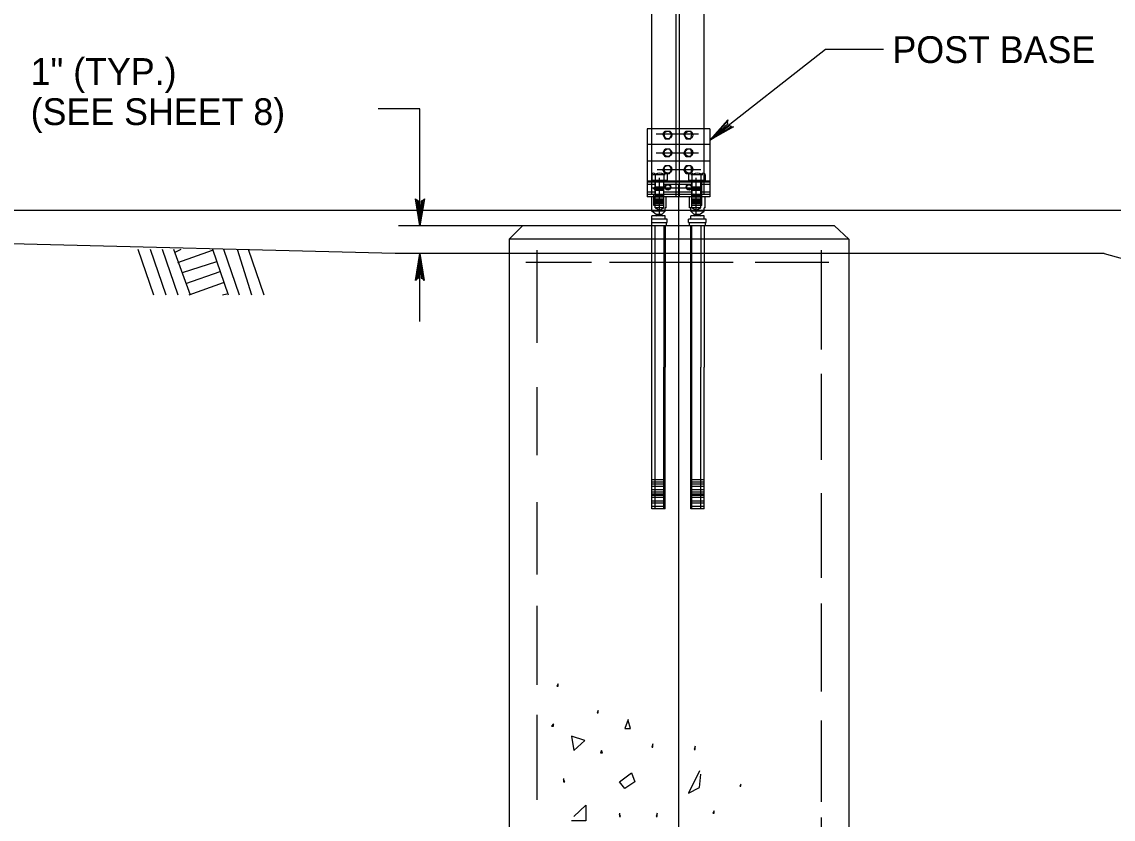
# Model space of a CAD drawing. Extents: x 637580 to 641008, y 294594 to 295782.
# Drawn here: x 637867.6 to 637989.9, y 295392.1 to 295481.5 of the extents above; entities that cross this region are included whole.
import ezdxf

# ---------------------------------------------------------------- set-up
doc = ezdxf.new("R2010")
doc.units = 0
for name, color, linetype in [('1', 7, 'Continuous'), ('2', 7, 'Continuous'), ('3', 7, 'Continuous')]:
    doc.layers.add(name, color=color, linetype=linetype)

# ---------------------------------------------------------------- blocks, each defined once
blk = doc.blocks.new('RARROW')
at = {"layer": '3'}
blk.add_lwpolyline([(-2.2695, 0.285), (-2.184875, 0.12075), (0, 0), (-2.2695, 0.285), (-2.38575, 0.384625), (0, 0), (-2.183125, -0.108), (-2.262875, -0.2705), (0, 0), (-2.38575, -0.379125), (-2.262875, -0.2705)], dxfattribs=at)

msp = doc.modelspace()

# ---------------------------------------------------------------- linework, layer by layer
at = {"layer": '1'}
for p, q in [((637880.56, 295456), (637882.31, 295450.88)), ((637881.94, 295456), (637883.69, 295450.88)), ((637883.31, 295456), (637885.06, 295450.88)), ((637884.56, 295456), (637886.44, 295450.88)), ((637884.69, 295455.63), (637885.44, 295456)), ((637885.06, 295454.5), (637888.94, 295455.88)), ((637888.94, 295456), (637890.69, 295450.88)), ((637890.19, 295456), (637891.94, 295450.88)), ((637891.69, 295456), (637893.31, 295450.88)), ((637892.94, 295456), (637894.69, 295450.88)), ((637885.56, 295453.38), (637889.44, 295454.63)), ((637885.94, 295452.13), (637889.81, 295453.5)), ((637886.31, 295450.88), (637890.19, 295452.25)), ((637890.06, 295450.88), (637890.56, 295451))]:
    msp.add_line(p, q, dxfattribs=at)
at = {"layer": '2'}
for p, q in [((637940.94, 295461.88), (637940.94, 295676.88)), ((637941.31, 295461.88), (637941.31, 295676.88)), ((637938.19, 295469.5), (637938.19, 295549.5)), ((637944.06, 295469.5), (637944.06, 295549.5)), ((637957.69, 295478.38), (637944.69, 295468.24)), ((637964.19, 295478.38), (637957.69, 295478.38)), ((637912.19, 295471.75), (637907.5, 295471.75)), ((637912.19, 295458.63), (637912.19, 295471.75)), ((637944.69, 295469.5), (637937.69, 295469.5)), ((637937.69, 295469.5), (637937.69, 295462.13)), ((637938.19, 295462.13), (637938.19, 295469.5)), ((637939.44, 295468.88), (637939.69, 295469.25)), ((637939.56, 295468.88), (637939.69, 295469.25)), ((637939.69, 295469.25), (637940.19, 295469.25)), ((637939.69, 295469.25), (637940.19, 295469.25)), ((637940.19, 295469.25), (637940.44, 295468.88)), ((637940.44, 295468.88), (637940.19, 295469.25)), ((637941.81, 295468.88), (637942.06, 295469.25)), ((637941.81, 295468.88), (637942.06, 295469.25)), ((637942.06, 295469.25), (637942.56, 295469.25)), ((637942.06, 295469.25), (637942.56, 295469.25)), ((637942.56, 295469.25), (637942.69, 295468.88)), ((637942.69, 295468.88), (637942.56, 295469.25)), ((637944.06, 295462.13), (637944.06, 295469.5)), ((637944.69, 295469.5), (637944.69, 295462.13)), ((637943.44, 295468.88), (637938.69, 295468.88)), ((637939.69, 295468.38), (637939.44, 295468.88)), ((637939.56, 295468.88), (637939.69, 295468.38)), ((637939.69, 295468.38), (637940.19, 295468.38)), ((637939.69, 295468.38), (637940.19, 295468.38)), ((637939.94, 295468.88), (637939.94, 295468.88)), ((637939.94, 295468.88), (637939.94, 295468.88)), ((637939.94, 295468.88), (637939.94, 295468.88)), ((637940.19, 295468.38), (637940.44, 295468.88)), ((637940.19, 295468.38), (637940.44, 295468.88)), ((637941.81, 295468.88), (637942.06, 295468.38)), ((637942.06, 295468.38), (637941.81, 295468.88)), ((637942.06, 295468.38), (637942.56, 295468.38)), ((637942.06, 295468.38), (637942.56, 295468.38)), ((637942.31, 295468.88), (637942.31, 295468.88)), ((637942.31, 295468.88), (637942.31, 295468.88)), ((637942.31, 295468.88), (637942.31, 295468.88)), ((637942.56, 295468.38), (637942.69, 295468.88)), ((637942.56, 295468.38), (637942.69, 295468.88)), ((637944.69, 295467.75), (637937.69, 295467.75)), ((637943.44, 295466.75), (637938.69, 295466.75)), ((637939.44, 295466.75), (637939.69, 295467.25)), ((637939.69, 295466.38), (637939.44, 295466.75)), ((637939.56, 295466.75), (637939.69, 295467.25)), ((637939.56, 295466.75), (637939.69, 295466.38)), ((637939.69, 295467.25), (637940.19, 295467.25)), ((637939.69, 295467.25), (637940.19, 295467.25)), ((637939.94, 295466.75), (637939.94, 295466.75)), ((637939.94, 295466.75), (637939.94, 295466.75)), ((637939.94, 295466.75), (637939.94, 295466.75)), ((637940.19, 295467.25), (637940.44, 295466.75)), ((637940.44, 295466.75), (637940.19, 295467.25)), ((637940.19, 295466.38), (637940.44, 295466.75)), ((637940.19, 295466.38), (637940.44, 295466.75)), ((637941.81, 295466.75), (637942.06, 295467.25)), ((637941.81, 295466.75), (637942.06, 295467.25)), ((637941.81, 295466.75), (637942.06, 295466.38)), ((637942.06, 295466.38), (637941.81, 295466.75)), ((637942.06, 295467.25), (637942.56, 295467.25)), ((637942.06, 295467.25), (637942.56, 295467.25)), ((637942.31, 295466.75), (637942.31, 295466.75)), ((637942.31, 295466.75), (637942.31, 295466.75)), ((637942.31, 295466.75), (637942.31, 295466.75)), ((637942.56, 295467.25), (637942.69, 295466.75)), ((637942.69, 295466.75), (637942.56, 295467.25)), ((637942.56, 295466.38), (637942.69, 295466.75)), ((637942.56, 295466.38), (637942.69, 295466.75)), ((637944.69, 295465.88), (637937.69, 295465.88)), ((637939.69, 295466.38), (637940.19, 295466.38)), ((637939.69, 295466.38), (637940.19, 295466.38)), ((637942.06, 295466.38), (637942.56, 295466.38)), ((637942.06, 295466.38), (637942.56, 295466.38)), ((637938.19, 295464.38), (637938.19, 295464.38)), ((637938.19, 295464.38), (637938.19, 295463.75)), ((637938.31, 295464.38), (637938.31, 295464.38)), ((637938.31, 295464.38), (637938.56, 295464.38)), ((637938.56, 295464.38), (637938.56, 295463.75)), ((637938.56, 295464.38), (637939.56, 295464.38)), ((637938.56, 295464.38), (637938.56, 295464.38)), ((637943.69, 295464.88), (637938.81, 295464.88)), ((637939.06, 295464.38), (637939.06, 295464.38)), ((637939.44, 295464.88), (637939.69, 295465.38)), ((637939.69, 295464.5), (637939.44, 295464.88)), ((637939.56, 295464.88), (637939.69, 295465.38)), ((637939.56, 295464.88), (637939.69, 295464.5)), ((637939.56, 295464.38), (637939.56, 295463.75)), ((637939.56, 295464.38), (637939.56, 295464.38)), ((637939.56, 295464.38), (637939.69, 295464.38)), ((637939.69, 295465.38), (637940.19, 295465.38)), ((637939.69, 295465.38), (637940.19, 295465.38)), ((637939.69, 295464.5), (637940.19, 295464.5)), ((637939.69, 295464.5), (637940.19, 295464.5)), ((637939.69, 295464.38), (637939.69, 295464.38)), ((637939.94, 295464.88), (637939.94, 295464.88)), ((637939.94, 295464.88), (637939.94, 295464.88)), ((637939.94, 295464.88), (637939.94, 295464.88)), ((637939.94, 295464.38), (637939.94, 295464.38)), ((637939.94, 295464.38), (637939.94, 295463.75)), ((637940.19, 295465.38), (637940.44, 295464.88)), ((637940.44, 295464.88), (637940.19, 295465.38)), ((637940.19, 295464.5), (637940.44, 295464.88)), ((637940.19, 295464.5), (637940.44, 295464.88)), ((637941.81, 295464.88), (637942.06, 295465.38)), ((637941.81, 295464.88), (637942.06, 295465.38)), ((637941.81, 295464.88), (637942.06, 295464.5)), ((637942.06, 295464.5), (637941.81, 295464.88)), ((637942.06, 295465.38), (637942.56, 295465.38)), ((637942.06, 295465.38), (637942.56, 295465.38)), ((637942.06, 295464.5), (637942.56, 295464.5)), ((637942.06, 295464.5), (637942.56, 295464.5)), ((637942.31, 295464.88), (637942.31, 295464.88)), ((637942.31, 295464.88), (637942.31, 295464.88)), ((637942.31, 295464.88), (637942.31, 295464.88)), ((637942.31, 295464.38), (637942.31, 295464.38)), ((637942.31, 295464.38), (637942.31, 295463.75)), ((637942.56, 295465.38), (637942.69, 295464.88)), ((637942.69, 295464.88), (637942.56, 295465.38)), ((637942.56, 295464.5), (637942.69, 295464.88)), ((637942.56, 295464.5), (637942.69, 295464.88)), ((637942.56, 295464.38), (637942.56, 295464.38)), ((637942.56, 295464.38), (637942.69, 295464.38)), ((637942.69, 295464.38), (637942.69, 295463.75)), ((637942.69, 295464.38), (637943.69, 295464.38)), ((637942.69, 295464.38), (637942.69, 295464.38)), ((637943.19, 295464.38), (637943.19, 295464.38)), ((637943.69, 295464.38), (637943.69, 295463.75)), ((637943.69, 295464.38), (637943.69, 295464.38)), ((637943.69, 295464.38), (637943.94, 295464.38)), ((637943.94, 295464.38), (637943.94, 295464.38)), ((637944.19, 295464.38), (637944.19, 295464.38)), ((637944.19, 295464.38), (637944.19, 295463.75)), ((637938.56, 295463.63), (637937.69, 295463.63)), ((637944.69, 295463.5), (637937.69, 295463.5)), ((637938.56, 295463.25), (637937.69, 295463.25)), ((637938.19, 295463.75), (637939.94, 295463.75)), ((637938.19, 295463.63), (637938.19, 295463.75)), ((637938.19, 295463.63), (637939.69, 295463.63)), ((637938.56, 295463), (637938.56, 295463.75)), ((637938.56, 295463.63), (637938.56, 295461.88)), ((637939.06, 295460), (637939.06, 295464)), ((637939.06, 295463.63), (637939.06, 295463.63)), ((637939.06, 295463.63), (637939.06, 295463.63)), ((637939.56, 295463), (637939.56, 295463.75)), ((637939.56, 295461.88), (637939.56, 295463.63)), ((637942.69, 295463.63), (637939.56, 295463.63)), ((637942.69, 295463.25), (637939.56, 295463.25)), ((637939.69, 295463.63), (637939.81, 295463.75)), ((637941.19, 295463.25), (637941.19, 295379)), ((637942.31, 295463.75), (637944.19, 295463.75)), ((637942.44, 295463.63), (637942.44, 295463.75)), ((637942.44, 295463.63), (637944.06, 295463.63)), ((637942.69, 295463), (637942.69, 295463.75)), ((637942.69, 295463.63), (637942.69, 295461.88)), ((637943.19, 295460), (637943.19, 295464)), ((637943.19, 295463.63), (637943.19, 295463.63)), ((637943.19, 295463.63), (637943.19, 295463.63)), ((637943.69, 295463), (637943.69, 295463.75)), ((637943.81, 295461.88), (637943.81, 295463.63)), ((637944.69, 295463.63), (637943.81, 295463.63)), ((637944.69, 295463.25), (637943.81, 295463.25)), ((637944.06, 295463.63), (637944.06, 295463.75)), ((637938.56, 295462.38), (637937.69, 295462.38)), ((637944.69, 295462.13), (637937.69, 295462.13)), ((637937.69, 295462.13), (637937.69, 295461.88)), ((637944.31, 295461.88), (637937.69, 295461.88)), ((637938.56, 295461.88), (637937.69, 295461.88)), ((637938.19, 295462.88), (637943.56, 295462.88)), ((637938.19, 295460.63), (637938.19, 295461.88)), ((637939.81, 295461.88), (637938.19, 295461.88)), ((637938.44, 295462.88), (637938.56, 295463)), ((637938.44, 295462.88), (637939.56, 295462.88)), ((637938.44, 295462.75), (637938.44, 295462.88)), ((637938.44, 295462.75), (637939.56, 295462.75)), ((637938.56, 295462.63), (637938.44, 295462.75)), ((637938.44, 295462.13), (637939.56, 295462.13)), ((637938.44, 295461.13), (637938.44, 295462.13)), ((637938.44, 295460.88), (637938.44, 295461.88)), ((637938.44, 295461.88), (637939.56, 295461.88)), ((637938.56, 295463), (637939.56, 295463)), ((637938.56, 295462.13), (637938.56, 295462.63)), ((637938.56, 295462.63), (637939.56, 295462.63)), ((637938.56, 295462), (637939.44, 295462)), ((637938.56, 295460.63), (637938.56, 295461.88)), ((637939.06, 295462.88), (637939.06, 295462.88)), ((637939.06, 295461.88), (637939.06, 295461.88)), ((637939.06, 295461.88), (637939.06, 295461.88)), ((637939.56, 295462.88), (637939.56, 295463)), ((637939.56, 295462.75), (637939.56, 295462.88)), ((637939.56, 295462.63), (637939.56, 295462.75)), ((637939.56, 295462.13), (637939.56, 295462.63)), ((637942.69, 295462.38), (637939.56, 295462.38)), ((637939.56, 295461.13), (637939.56, 295462.13)), ((637942.69, 295461.88), (637939.56, 295461.88)), ((637939.56, 295460.88), (637939.56, 295461.88)), ((637939.56, 295460.63), (637939.56, 295461.88)), ((637939.81, 295460.63), (637939.81, 295461.88)), ((637939.94, 295462.88), (637939.94, 295462.88)), ((637941.19, 295462.13), (637941.19, 295462.13)), ((637941.19, 295461.88), (637941.19, 295461.88)), ((637941.19, 295461.88), (637941.19, 295461.88)), ((637942.31, 295462.88), (637942.31, 295462.88)), ((637942.44, 295460.63), (637942.44, 295461.88)), ((637944.19, 295461.88), (637942.44, 295461.88)), ((637942.69, 295462.88), (637942.69, 295463)), ((637942.69, 295463), (637943.69, 295463)), ((637942.69, 295462.88), (637943.81, 295462.88)), ((637942.69, 295462.75), (637942.69, 295462.88)), ((637942.69, 295462.75), (637943.81, 295462.75)), ((637942.69, 295462.63), (637942.69, 295462.75)), ((637942.69, 295462.13), (637942.69, 295462.63)), ((637942.69, 295462.63), (637943.69, 295462.63)), ((637942.69, 295462.13), (637943.81, 295462.13)), ((637942.69, 295461.13), (637942.69, 295462.13)), ((637942.69, 295462), (637943.69, 295462)), ((637942.69, 295460.88), (637942.69, 295461.88)), ((637942.69, 295460.63), (637942.69, 295461.88)), ((637942.69, 295461.88), (637943.81, 295461.88)), ((637943.19, 295462.88), (637943.19, 295462.88)), ((637943.19, 295461.88), (637943.19, 295461.88)), ((637943.19, 295461.88), (637943.19, 295461.88)), ((637943.81, 295462.88), (637943.69, 295463)), ((637943.69, 295462.63), (637943.81, 295462.75)), ((637943.69, 295462.13), (637943.69, 295462.63)), ((637943.69, 295460.63), (637943.69, 295461.88)), ((637943.81, 295462.75), (637943.81, 295462.88)), ((637944.69, 295462.38), (637943.81, 295462.38)), ((637943.81, 295461.13), (637943.81, 295462.13)), ((637944.69, 295461.88), (637943.81, 295461.88)), ((637943.81, 295460.88), (637943.81, 295461.88)), ((637944.19, 295460.63), (637944.19, 295461.88)), ((637944.69, 295462.13), (637944.69, 295461.88)), ((637938.19, 295460.25), (637938.19, 295460.63)), ((637938.19, 295460.63), (637938.19, 295460.63)), ((637938.44, 295461.5), (637939.56, 295461.5)), ((637938.44, 295461.38), (637939.56, 295461.38)), ((637938.44, 295461.13), (637939.56, 295461.13)), ((637939.56, 295460.88), (637938.44, 295460.88)), ((637938.56, 295461.63), (637939.44, 295461.63)), ((637938.56, 295461.38), (637939.44, 295461.38)), ((637938.56, 295461.25), (637939.44, 295461.25)), ((637939.56, 295460.63), (637938.56, 295460.63)), ((637938.56, 295460.63), (637939.06, 295460.38)), ((637939.06, 295461.13), (637939.06, 295461.13)), ((637939.06, 295460.38), (637939.56, 295460.63)), ((637939.69, 295460.25), (637939.69, 295460.63)), ((637939.81, 295460.63), (637939.69, 295460.63)), ((637942.56, 295460.63), (637942.44, 295460.63)), ((637942.56, 295460.25), (637942.56, 295460.63)), ((637942.69, 295461.63), (637943.69, 295461.63)), ((637942.69, 295461.5), (637943.81, 295461.5)), ((637942.69, 295461.38), (637943.81, 295461.38)), ((637942.69, 295461.38), (637943.69, 295461.38)), ((637942.69, 295461.25), (637943.69, 295461.25)), ((637942.69, 295461.13), (637943.81, 295461.13)), ((637943.81, 295460.88), (637942.69, 295460.88)), ((637943.69, 295460.63), (637942.69, 295460.63)), ((637942.69, 295460.63), (637943.19, 295460.38)), ((637943.19, 295461.13), (637943.19, 295461.13)), ((637943.19, 295460.38), (637943.69, 295460.63)), ((637944.06, 295460.25), (637944.06, 295460.63)), ((637944.19, 295460.63), (637944.06, 295460.63)), ((637909.44, 295455.5), (637719.19, 295460.38)), ((637724.69, 295460.38), (638231.69, 295460.38)), ((637938.69, 295459.88), (637938.19, 295460.25)), ((637939.69, 295460.25), (637938.19, 295460.25)), ((637938.19, 295459.38), (637938.19, 295459.75)), ((637939.69, 295459.75), (637938.19, 295459.75)), ((637939.94, 295459.38), (637938.19, 295459.38)), ((637938.19, 295459), (637938.19, 295459.38)), ((637938.69, 295459.88), (637938.69, 295459.88)), ((637939.31, 295459.88), (637938.69, 295459.88)), ((637939.06, 295460.38), (637939.06, 295460.38)), ((637939.06, 295459.38), (637939.06, 295459.38)), ((637939.31, 295459.88), (637939.69, 295460.25)), ((637939.31, 295459.88), (637939.31, 295459.88)), ((637939.69, 295459.38), (637939.69, 295459.75)), ((637939.94, 295459), (637939.94, 295459.38)), ((637941.19, 295460.38), (637941.19, 295460.38)), ((637944.31, 295459.38), (637942.31, 295459.38)), ((637942.31, 295459), (637942.31, 295459.38)), ((637942.94, 295459.88), (637942.56, 295460.25)), ((637944.06, 295460.25), (637942.56, 295460.25)), ((637942.56, 295459.38), (637942.56, 295459.75)), ((637944.06, 295459.75), (637942.56, 295459.75)), ((637942.94, 295459.88), (637942.94, 295459.88)), ((637943.56, 295459.88), (637942.94, 295459.88)), ((637943.19, 295460.38), (637943.19, 295460.38)), ((637943.19, 295459.38), (637943.19, 295459.38)), ((637943.56, 295459.88), (637944.06, 295460.25)), ((637943.56, 295459.88), (637943.56, 295459.88)), ((637944.06, 295459.38), (637944.06, 295459.75)), ((637944.31, 295459), (637944.31, 295459.38)), ((637923.69, 295458.63), (637909.81, 295458.63)), ((637922.19, 295457.13), (637923.69, 295458.63)), ((637958.69, 295458.63), (637923.69, 295458.63)), ((637938.19, 295459), (637939.94, 295459)), ((637938.19, 295458.63), (637938.19, 295459)), ((637938.19, 295442.75), (637938.19, 295458.63)), ((637938.56, 295442.75), (637938.56, 295458.63)), ((637939.06, 295458.63), (637939.06, 295458.63)), ((637939.56, 295458.63), (637939.56, 295442.75)), ((637939.69, 295458.63), (637939.69, 295442.75)), ((637939.81, 295459), (637939.81, 295458.63)), ((637941.19, 295458.63), (637941.19, 295458.63)), ((637941.19, 295458.63), (637941.19, 295458.63)), ((637942.31, 295459), (637944.31, 295459)), ((637942.44, 295458.63), (637942.44, 295459)), ((637942.56, 295442.75), (637942.56, 295458.63)), ((637942.69, 295442.75), (637942.69, 295458.63)), ((637943.19, 295458.63), (637943.19, 295458.63)), ((637943.69, 295458.63), (637943.69, 295442.75)), ((637944.06, 295458.63), (637944.06, 295442.75)), ((637944.19, 295459), (637944.19, 295458.63)), ((637958.69, 295458.63), (637958.06, 295458.63)), ((637958.69, 295458.63), (637960.31, 295457.13)), ((637960.31, 295457.13), (637922.19, 295457.13)), ((637922.19, 295457.13), (637922.19, 295454.75)), ((637960.31, 295457.13), (637960.31, 295454.13)), ((637925.31, 295455.88), (637925.31, 295445.5)), ((637957.19, 295455.88), (637957.19, 295444.75)), ((637988.94, 295455.5), (637909.44, 295455.5)), ((637912.19, 295447.88), (637912.19, 295455.5)), ((637922.19, 295454.75), (637922.19, 295382.38)), ((637931.44, 295454.5), (637924.06, 295454.5)), ((637947.31, 295454.5), (637933.44, 295454.5)), ((637958.06, 295454.5), (637949.81, 295454.5)), ((637988.94, 295455.5), (638183.94, 295401.38)), ((637960.31, 295454.13), (637960.31, 295382.38)), ((637938.19, 295426.88), (637938.19, 295442.75)), ((637938.56, 295426.88), (637938.56, 295442.75)), ((637939.56, 295426.88), (637939.56, 295442.75)), ((637939.69, 295426.88), (637939.69, 295442.75)), ((637942.56, 295426.88), (637942.56, 295442.75)), ((637942.69, 295426.88), (637942.69, 295442.75)), ((637943.69, 295426.88), (637943.69, 295442.75)), ((637944.06, 295426.88), (637944.06, 295442.75)), ((637957.19, 295442), (637957.19, 295432.38)), ((637925.31, 295440.5), (637925.31, 295432.88)), ((637939.69, 295430.13), (637938.19, 295430.13)), ((637944.06, 295430.13), (637942.56, 295430.13)), ((637939.69, 295429.88), (637938.19, 295429.88)), ((637939.69, 295429.63), (637938.19, 295429.63)), ((637939.69, 295429.38), (637938.19, 295429.38)), ((637939.69, 295429), (637938.19, 295429)), ((637939.69, 295428.75), (637938.19, 295428.75)), ((637944.06, 295429.88), (637942.56, 295429.88)), ((637944.06, 295429.63), (637942.56, 295429.63)), ((637944.06, 295429.38), (637942.56, 295429.38)), ((637944.06, 295429), (637942.56, 295429)), ((637944.06, 295428.75), (637942.56, 295428.75)), ((637925.31, 295427.63), (637925.31, 295419.5)), ((637939.69, 295428.5), (637938.19, 295428.5)), ((637939.69, 295428.38), (637938.19, 295428.38)), ((637939.69, 295428.13), (637938.19, 295428.13)), ((637939.69, 295427.75), (637938.19, 295427.75)), ((637944.06, 295428.5), (637942.56, 295428.5)), ((637944.06, 295428.38), (637942.56, 295428.38)), ((637944.06, 295428.13), (637942.56, 295428.13)), ((637944.06, 295427.75), (637942.56, 295427.75)), ((637957.19, 295428.63), (637957.19, 295419.13)), ((637939.69, 295427.5), (637938.19, 295427.5)), ((637939.69, 295427.13), (637938.19, 295427.13)), ((637939.69, 295426.88), (637938.19, 295426.88)), ((637944.06, 295427.5), (637942.56, 295427.5)), ((637944.06, 295427.13), (637942.56, 295427.13)), ((637944.06, 295426.88), (637942.56, 295426.88)), ((637925.31, 295416), (637925.31, 295407.13)), ((637957.19, 295416.25), (637957.19, 295406.38)), ((637925.31, 295403.75), (637925.31, 295394.25)), ((637957.19, 295403.13), (637957.19, 295394)), ((637957.19, 295392.25), (637957.19, 295385.25))]:
    msp.add_line(p, q, dxfattribs=at)
for points in [[(637927.69, 295407.25), (637927.56, 295407), (637927.69, 295407), (637927.69, 295407.25)], [(637932.19, 295404.25), (637932.06, 295404), (637932.19, 295404), (637932.19, 295404.25)], [(637935.56, 295403.25), (637935.19, 295402.25), (637935.81, 295402.25), (637935.56, 295403.13)], [(637927.19, 295402.75), (637926.94, 295402.5), (637927.19, 295402.5), (637927.19, 295402.75)], [(637929.19, 295401.38), (637929.44, 295399.75), (637930.69, 295400.88), (637929.19, 295401.38)], [(637932.56, 295399.75), (637932.44, 295399.5), (637932.69, 295399.5), (637932.56, 295399.75)], [(637938.31, 295400.5), (637938.19, 295400.13), (637938.31, 295400.13), (637938.31, 295400.38)], [(637943.06, 295400.25), (637942.94, 295399.88), (637943.06, 295399.88), (637943.06, 295400.13)], [(637934.56, 295396.25), (637935.94, 295397.25), (637936.31, 295396.25), (637935.19, 295395.5), (637934.56, 295396.25)], [(637943.56, 295397.5), (637942.31, 295395), (637943.56, 295395.63), (637943.69, 295397.13)], [(637928.31, 295396.63), (637928.31, 295396.25), (637928.44, 295396.25), (637928.31, 295396.5)], [(637948.19, 295396), (637948.06, 295395.75), (637948.19, 295395.75), (637948.19, 295395.88)], [(637929.44, 295392.38), (637930.81, 295393.63), (637930.81, 295391.88), (637929.19, 295391.88)], [(637934.56, 295392.75), (637934.56, 295392.38), (637934.69, 295392.38), (637934.56, 295392.63)], [(637938.81, 295392.75), (637938.69, 295392.38), (637938.81, 295392.38), (637938.81, 295392.63)], [(637945.19, 295393), (637945.06, 295392.75), (637945.19, 295392.75), (637945.19, 295393)]]:
    msp.add_lwpolyline(points, dxfattribs=at)
for centre, major_axis in [((637940, 295468.8), (0, 0.432)), ((637940, 295468.8), (0, -0.432)), ((637942.38, 295468.8), (0, 0.432)), ((637942.38, 295468.8), (0, -0.432)), ((637940, 295466.81), (0, 0.432)), ((637940, 295466.81), (0, -0.432)), ((637942.38, 295466.81), (0, 0.432)), ((637942.38, 295466.81), (0, -0.432)), ((637940, 295464.95), (0, 0.432)), ((637940, 295464.95), (0, -0.432)), ((637942.38, 295464.95), (0, 0.432)), ((637942.38, 295464.95), (0, -0.432)), ((637940, 295462.96), (0, 0.331)), ((637940, 295462.96), (0, 0.265)), ((637942.38, 295462.96), (0, 0.331)), ((637942.38, 295462.96), (0, 0.265))]:
    msp.add_ellipse(centre, major_axis=major_axis, ratio=0.996388, dxfattribs=at)
for centre, major_axis, start_param, end_param in [((637938.39, 295464.25), (0, -0.259), 2.218404, 4.064781), ((637939.07, 295463.34), (0, -1.17), 2.718335, 3.56485), ((637939.76, 295464.24), (0, -0.265), 2.228521, 4.054665), ((637942.62, 295464.25), (0, -0.259), 2.218404, 4.064781), ((637943.3, 295463.34), (0, -1.17), 2.718335, 3.56485), ((637943.99, 295464.24), (0, -0.265), 2.228521, 4.054665), ((637938.55, 295462.22), (0, 0.0993), 3.141593, 4.712389), ((637939.6, 295462.22), (0, -0.0993), 4.712389, 6.283185), ((637942.78, 295462.22), (0, 0.0993), 3.141593, 4.712389), ((637943.83, 295462.22), (0, -0.0993), 4.712389, 6.283185), ((637938.71, 295459.78), (0, 0.0662), 3.141593, 4.712389), ((637939.44, 295459.78), (0, -0.0662), 4.712389, 6.283185), ((637942.94, 295459.78), (0, 0.0662), 3.141593, 4.712389), ((637943.67, 295459.78), (0, -0.0662), 4.712389, 6.283185)]:
    msp.add_ellipse(centre, major_axis=major_axis, ratio=0.996388, start_param=start_param, end_param=end_param, dxfattribs=at)

# ---------------------------------------------------------------- block references
at = {"layer": '2', "xscale": 1.2574347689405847}
for p, yscale, rotation in [((637944.69, 295468.24), 1.3092961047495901, -141.2085354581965), ((637912.19, 295458.63), 1.3092961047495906, -90.00000000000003), ((637912.19, 295455.5), 1.3092961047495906, 89.99999999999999)]:
    msp.add_blockref('RARROW', p, dxfattribs=dict(at, yscale=yscale, rotation=rotation))

# ---------------------------------------------------------------- texts
at = {"layer": '1'}
msp.add_text('POST BASE', height=3, dxfattribs=at).set_placement((637965.19, 295476.88))
at = {"layer": '3'}
for s, p in [('1" (TYP.)', (637868.55, 295474.42)), ('(SEE SHEET 8)', (637868.55, 295469.92))]:
    msp.add_text(s, height=3, dxfattribs=at).set_placement(p)

doc.saveas('drawing.dxf')
